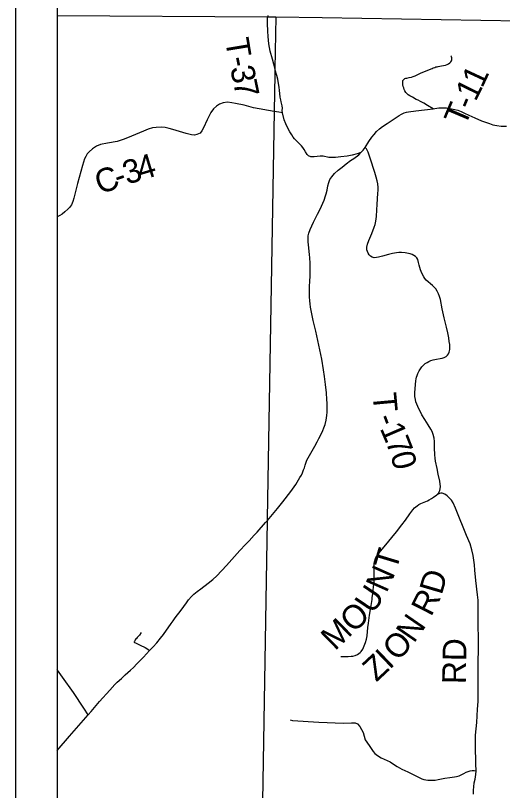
# Model space of a CAD drawing. Extents: x -10 to 158, y 8 to 33.
# Drawn here: x 148.504 to 149.672, y 28.282 to 30.14 of the extents above; entities that cross this region are included whole.
import ezdxf

# ---------------------------------------------------------------- set-up
doc = ezdxf.new("R2010")
doc.units = 0
for name, color, linetype in [('GM_X_County_Road', 7, 'Continuous'), ('GM_X_County_Road_Text', 7, 'Continuous'), ('GM_X_Township_Road', 7, 'Continuous'), ('GM_X_Township_Road_Text', 7, 'Continuous'), ('GM_X_Township_Text', 7, 'Continuous'), ('SH_Data', 7, 'Continuous')]:
    doc.layers.add(name, color=color, linetype=linetype)

msp = doc.modelspace()

# ---------------------------------------------------------------- linework, layer by layer
at = {"layer": 'GM_X_County_Road'}
for points in [[(149.1243, 29.9099), (149.0748, 29.9186), (149.0523, 29.9246), (149.032, 29.9293), (149.0225, 29.9306), (149.0121, 29.9318), (149.0023, 29.9303), (148.9936, 29.9271), (148.9857, 29.9228), (148.9789, 29.9163), (148.9726, 29.9075), (148.964, 29.8896), (148.955, 29.8705), (148.9505, 29.863), (148.9465, 29.858), (148.9392, 29.8543), (148.9331, 29.8531), (148.9263, 29.8535), (148.9135, 29.8566), (148.881, 29.8667), (148.8727, 29.8691), (148.8626, 29.8711), (148.8541, 29.8721), (148.8411, 29.8717), (148.8322, 29.8702), (148.8221, 29.8674), (148.8107, 29.8623), (148.8011, 29.8588), (148.7824, 29.8508), (148.7648, 29.8434), (148.7479, 29.8382), (148.7246, 29.834), (148.7076, 29.8304), (148.6984, 29.8265), (148.6884, 29.8199), (148.6804, 29.8131), (148.6758, 29.8079), (148.6722, 29.802), (148.6694, 29.7961), (148.6644, 29.7802), (148.6527, 29.7367), (148.6435, 29.7021), (148.6413, 29.6942), (148.6382, 29.6862), (148.6333, 29.6798), (148.6291, 29.6755), (148.6224, 29.6692), (148.6159, 29.6639), (148.6099, 29.66), (148.6038, 29.6571)], [(149.3325, 29.8115), (149.3234, 29.8082), (149.3113, 29.8049), (149.2997, 29.8028), (149.2842, 29.8012), (149.2716, 29.7998), (149.2636, 29.7994), (149.2558, 29.7996), (149.2421, 29.8025), (149.2347, 29.8026), (149.2203, 29.8009), (149.2121, 29.8014), (149.2066, 29.8036), (149.2037, 29.8067), (149.1996, 29.8129), (149.1963, 29.8188), (149.1934, 29.8234), (149.1901, 29.8275), (149.1828, 29.835), (149.1795, 29.8382), (149.1735, 29.8444), (149.1703, 29.8483), (149.1664, 29.8534), (149.1617, 29.8608), (149.1573, 29.8694), (149.1526, 29.8799), (149.1487, 29.8901), (149.144, 29.9067), (149.1353, 29.9083), (149.1243, 29.9099)], [(149.3427, 29.8238), (149.3513, 29.8378), (149.3586, 29.848), (149.3639, 29.8542), (149.3697, 29.8614), (149.3774, 29.8681), (149.3846, 29.8735), (149.3958, 29.8807), (149.4077, 29.889), (149.424, 29.9001), (149.4296, 29.9035), (149.4365, 29.9066), (149.4419, 29.908), (149.4464, 29.9086), (149.4642, 29.9111), (149.5055, 29.9164), (149.5099, 29.917), (149.5191, 29.9182), (149.5287, 29.9187), (149.5379, 29.9184), (149.5494, 29.9165), (149.5577, 29.9149), (149.5646, 29.9126), (149.5729, 29.9096), (149.5809, 29.9057), (149.591, 29.9011), (149.6056, 29.8946), (149.622, 29.8877), (149.6411, 29.8806), (149.6492, 29.8779), (149.6584, 29.8759), (149.6686, 29.8744), (149.682, 29.8743)], [(149.0833, 28.9014), (149.1037, 28.924), (149.108, 28.9288), (149.132, 28.9574), (149.1455, 28.9738), (149.1641, 28.9986), (149.1761, 29.015), (149.1863, 29.0321), (149.1896, 29.0374), (149.1922, 29.0434), (149.1951, 29.0502), (149.1969, 29.055), (149.1988, 29.0614), (149.2009, 29.069), (149.2029, 29.0736), (149.2056, 29.0791), (149.2216, 29.1076), (149.2275, 29.1179), (149.2315, 29.1253), (149.2369, 29.1357), (149.2412, 29.1447), (149.2438, 29.1514), (149.2464, 29.159), (149.2488, 29.1696), (149.2504, 29.1807), (149.2513, 29.1888), (149.2512, 29.1964), (149.2513, 29.2103), (149.251, 29.2191), (149.2496, 29.2353), (149.2475, 29.2548), (149.2453, 29.2742), (149.2429, 29.2901), (149.2387, 29.316), (149.2316, 29.3492), (149.2242, 29.3831), (149.2181, 29.4086), (149.2132, 29.4325), (149.2116, 29.4408), (149.2104, 29.4485), (149.2096, 29.456), (149.2088, 29.4653), (149.2091, 29.478), (149.2093, 29.4905), (149.2096, 29.5028), (149.2105, 29.5147), (149.2107, 29.5322), (149.2104, 29.5451), (149.2097, 29.56), (149.2091, 29.5657), (149.2067, 29.5909), (149.206, 29.5966), (149.2057, 29.6011), (149.2057, 29.6061), (149.2063, 29.6118), (149.2076, 29.6182), (149.2104, 29.6269), (149.2144, 29.6353), (149.2189, 29.6442), (149.2284, 29.6633), (149.2348, 29.6753), (149.238, 29.683), (149.244, 29.6975), (149.2475, 29.7073), (149.2492, 29.7121), (149.2512, 29.721), (149.2534, 29.7314), (149.2554, 29.7394), (149.2581, 29.7468), (149.2623, 29.7534), (149.2689, 29.7609), (149.2778, 29.7692), (149.2873, 29.7766), (149.2973, 29.7844), (149.3078, 29.7919), (149.3157, 29.7972), (149.3272, 29.8055), (149.3325, 29.8115), (149.3378, 29.8172), (149.3427, 29.8238)], [(148.6038, 28.3779), (148.6336, 28.4119), (148.6449, 28.4246), (148.6778, 28.4628), (148.6851, 28.4709), (148.7057, 28.4948), (148.7299, 28.5224), (148.7421, 28.5357), (148.7476, 28.5412), (148.7578, 28.5505), (148.7669, 28.5586), (148.7794, 28.5698), (148.787, 28.5769), (148.7953, 28.5851), (148.8028, 28.5931), (148.8106, 28.6015), (148.8253, 28.6171), (148.8266, 28.6187), (148.8338, 28.6264), (148.8425, 28.636), (148.8517, 28.6465), (148.8588, 28.6554), (148.8772, 28.6821), (148.8817, 28.6886), (148.8868, 28.6957), (148.9012, 28.7141), (148.9139, 28.7319), (148.9191, 28.7386), (148.9264, 28.7468), (148.9318, 28.7521), (148.94, 28.7587), (148.9486, 28.7655), (148.9657, 28.7787), (148.9773, 28.7876), (148.9868, 28.7963), (149.0101, 28.821), (149.0422, 28.8568), (149.0557, 28.8712), (149.064, 28.8805), (149.0762, 28.8936), (149.0785, 28.8962), (149.0833, 28.9014)]]:
    msp.add_lwpolyline(points, dxfattribs=at)
at = {"layer": 'GM_X_Township_Road'}
for points in [[(149.1329, 29.9869), (149.1305, 29.9959), (149.127, 30.0091), (149.1264, 30.0116), (149.1205, 30.0354), (149.1145, 30.0547), (149.1113, 30.072), (149.1104, 30.0804), (149.1096, 30.0898), (149.1089, 30.1026), (149.1082, 30.1208), (149.1085, 30.1359)], [(149.1095, 30.1402), (149.1085, 30.1359)], [(149.5055, 29.9164), (149.4922, 29.9242), (149.4833, 29.9295), (149.4752, 29.9338), (149.4697, 29.9367), (149.4653, 29.9389), (149.456, 29.9438), (149.4499, 29.9472), (149.446, 29.9498), (149.4425, 29.9528), (149.4401, 29.9554), (149.4376, 29.9592), (149.4363, 29.9622), (149.4351, 29.9662), (149.4342, 29.9695), (149.4333, 29.9735), (149.4329, 29.9765), (149.4327, 29.9798), (149.4328, 29.9818), (149.4332, 29.9838), (149.4343, 29.9855), (149.436, 29.9873), (149.438, 29.9886), (149.4405, 29.9897), (149.4424, 29.99), (149.448, 29.991), (149.4535, 29.9921), (149.4577, 29.9933), (149.4626, 29.9956), (149.4769, 30.0022), (149.5031, 30.0128), (149.506, 30.0142), (149.5095, 30.0155), (149.5124, 30.0165), (149.515, 30.0172), (149.5177, 30.0178), (149.5214, 30.0184), (149.5258, 30.0191), (149.5308, 30.0199), (149.535, 30.0209), (149.539, 30.0223), (149.5426, 30.0239), (149.5457, 30.0263), (149.5478, 30.0285), (149.5495, 30.0316), (149.5502, 30.0338), (149.5506, 30.0366), (149.5504, 30.0387), (149.5501, 30.0408), (149.5492, 30.0423), (149.548, 30.0436)], [(149.144, 29.9067), (149.1437, 29.9119), (149.144, 29.918), (149.1434, 29.9236), (149.1411, 29.9333), (149.14, 29.938), (149.139, 29.9441), (149.1381, 29.9532), (149.1373, 29.9603), (149.1364, 29.9678), (149.135, 29.9771), (149.1329, 29.9869)], [(149.2844, 28.603), (149.2882, 28.6027), (149.2954, 28.6028), (149.3018, 28.6029), (149.3088, 28.6034), (149.3131, 28.604), (149.3187, 28.6055), (149.324, 28.6079), (149.3278, 28.6104), (149.3303, 28.6124), (149.3327, 28.6152), (149.3368, 28.6208), (149.3389, 28.6245), (149.3405, 28.6286), (149.3432, 28.6365), (149.3456, 28.6447), (149.3471, 28.6527), (149.3491, 28.6726), (149.3504, 28.6829), (149.3534, 28.7021), (149.3574, 28.7255), (149.3592, 28.7393), (149.3596, 28.7433), (149.3608, 28.7542), (149.3626, 28.7697), (149.3639, 28.7819), (149.3644, 28.7915), (149.3644, 28.8074), (149.3641, 28.8154), (149.3643, 28.823), (149.3645, 28.8268), (149.3655, 28.832), (149.3667, 28.8359), (149.3685, 28.8402), (149.3706, 28.8435), (149.3732, 28.8474), (149.3796, 28.8553), (149.3925, 28.8708), (149.4065, 28.8883), (149.4175, 28.9021), (149.4306, 28.9188), (149.4392, 28.93), (149.4497, 28.9447), (149.4566, 28.9544), (149.4613, 28.9597), (149.467, 28.9645), (149.4713, 28.967), (149.4762, 28.9695), (149.488, 28.9747), (149.4921, 28.9765), (149.4965, 28.9787), (149.5014, 28.9814), (149.5067, 28.9849), (149.5145, 28.9905), (149.5184, 28.9948), (149.5204, 28.9977), (149.5218, 29.0006), (149.5227, 29.0051), (149.5233, 29.0103), (149.5229, 29.0165), (149.5218, 29.0235), (149.5177, 29.0403), (149.515, 29.0535), (149.5117, 29.0711), (149.5103, 29.0781), (149.5095, 29.0866), (149.5091, 29.1033), (149.5092, 29.1096), (149.5087, 29.1181), (149.5079, 29.1262), (149.5059, 29.1349), (149.5031, 29.1426), (149.5, 29.1483), (149.4936, 29.1582), (149.4855, 29.171), (149.4789, 29.1822), (149.475, 29.1893), (149.4713, 29.1968), (149.4664, 29.2077), (149.4644, 29.2139), (149.4632, 29.2188), (149.462, 29.2262), (149.4619, 29.2314), (149.4621, 29.236), (149.4642, 29.2636), (149.4648, 29.2685), (149.4659, 29.2729), (149.4672, 29.2768), (149.4688, 29.2817), (149.472, 29.2875), (149.475, 29.2924), (149.4789, 29.2972), (149.4823, 29.3013), (149.4867, 29.3052), (149.4911, 29.308), (149.4955, 29.3105), (149.5, 29.3123), (149.5054, 29.3139), (149.5135, 29.3157), (149.5222, 29.3171), (149.5274, 29.3183), (149.5324, 29.3198), (149.5366, 29.3221), (149.5401, 29.3253), (149.5424, 29.3285), (149.5445, 29.3329), (149.5457, 29.339), (149.5457, 29.3456), (149.5454, 29.3514), (149.5444, 29.3586), (149.5435, 29.3668), (149.5411, 29.379), (149.538, 29.3927), (149.5325, 29.4149), (149.5274, 29.4362), (149.523, 29.4588), (149.5212, 29.4664), (149.5189, 29.4728), (149.5157, 29.4789), (149.5123, 29.4843), (149.5089, 29.488), (149.5042, 29.4925), (149.4892, 29.5053), (149.4859, 29.5089), (149.483, 29.5136), (149.4787, 29.5223), (149.4754, 29.5301), (149.4736, 29.5356), (149.4724, 29.5416), (149.4708, 29.5476), (149.4688, 29.555), (149.4662, 29.5589), (149.463, 29.5621), (149.4594, 29.5646), (149.4555, 29.5666), (149.4503, 29.5684), (149.439, 29.5706), (149.43, 29.5714), (149.4237, 29.5713), (149.4181, 29.5712), (149.408, 29.5693), (149.3986, 29.5667), (149.3841, 29.5627), (149.3744, 29.5601), (149.3697, 29.5593), (149.3646, 29.5591), (149.3593, 29.5605), (149.3554, 29.5628), (149.352, 29.5661), (149.3495, 29.5699), (149.348, 29.5738), (149.347, 29.5783), (149.347, 29.5845), (149.3483, 29.5919), (149.3513, 29.6007), (149.3586, 29.6174), (149.3646, 29.6322), (149.3669, 29.639), (149.3676, 29.6425), (149.3683, 29.6468), (149.3696, 29.6583), (149.3705, 29.6743), (149.3714, 29.6867), (149.3731, 29.7141), (149.3735, 29.7202), (149.3737, 29.7274), (149.3728, 29.7361), (149.3713, 29.7434), (149.3691, 29.7522), (149.3659, 29.7638), (149.3545, 29.7979), (149.3495, 29.8126), (149.3477, 29.8167), (149.3457, 29.8202), (149.3427, 29.8238)], [(149.6022, 28.273), (149.6027, 28.2825), (149.6033, 28.2903), (149.6044, 28.3), (149.6065, 28.3091), (149.6082, 28.3198), (149.6091, 28.329), (149.6084, 28.3455), (149.6077, 28.3893), (149.6076, 28.4145), (149.6102, 28.4443), (149.6118, 28.4769), (149.6136, 28.4953), (149.6138, 28.5294), (149.6134, 28.5528), (149.6134, 28.5915), (149.6145, 28.6178), (149.6147, 28.6447), (149.6135, 28.6797), (149.6138, 28.7036), (149.614, 28.7133), (149.6139, 28.7228), (149.6134, 28.7379), (149.6122, 28.7505), (149.6083, 28.7849), (149.6059, 28.8096), (149.605, 28.8226), (149.6014, 28.8453), (149.5988, 28.8588), (149.5942, 28.8727), (149.586, 28.893), (149.5795, 28.9088), (149.5673, 28.9383), (149.5593, 28.9587), (149.5538, 28.9713), (149.5498, 28.9775), (149.5469, 28.981), (149.544, 28.9834), (149.5391, 28.9879), (149.5334, 28.9924), (149.5277, 28.9947), (149.524, 28.9948), (149.5206, 28.9941), (149.5145, 28.9905)], [(148.8054, 28.6603), (148.8013, 28.6541), (148.7984, 28.6508), (148.7961, 28.6485), (148.794, 28.6464), (148.7922, 28.6449), (148.7909, 28.6429), (148.7898, 28.6407), (148.789, 28.6391), (148.7888, 28.638), (148.7888, 28.6369), (148.7896, 28.6362), (148.7919, 28.6353), (148.8026, 28.6302), (148.8146, 28.6246), (148.8213, 28.6204), (148.8253, 28.6171)], [(148.6778, 28.4628), (148.6678, 28.4787), (148.6426, 28.5162), (148.6167, 28.5536), (148.6047, 28.5703), (148.6038, 28.5715)], [(149.1627, 28.4514), (149.168, 28.4498), (149.2312, 28.4451), (149.2908, 28.443), (149.3097, 28.444), (149.3185, 28.4439), (149.3245, 28.4416), (149.3301, 28.4347), (149.3376, 28.4206), (149.3427, 28.4031), (149.3526, 28.3892), (149.3587, 28.3797), (149.3619, 28.3748), (149.366, 28.3704), (149.3719, 28.3652), (149.3809, 28.3599), (149.3956, 28.3534), (149.4024, 28.3503), (149.4082, 28.3466), (149.4195, 28.339), (149.4308, 28.3324), (149.4451, 28.3261), (149.4606, 28.3186), (149.4785, 28.3098), (149.4832, 28.3077), (149.4929, 28.3065), (149.502, 28.3061), (149.5106, 28.3065), (149.5181, 28.3077), (149.5336, 28.3109), (149.5457, 28.3129), (149.5569, 28.3144), (149.562, 28.315), (149.5679, 28.3164), (149.5729, 28.3193), (149.579, 28.3223), (149.585, 28.3252), (149.5898, 28.3271), (149.5946, 28.3285), (149.5993, 28.3295), (149.604, 28.3295), (149.6091, 28.329)]]:
    msp.add_lwpolyline(points, dxfattribs=at)
at = {"layer": 'GM_X_Township_Text'}
msp.add_line((148.6038, 30.1399), (148.6038, 27.4428), dxfattribs=at)
for points in [[(148.6038, 30.1399), (149.1083, 30.1364), (149.1287, 30.1368), (149.2397, 30.1351), (150.0007, 30.1222), (150.0269, 30.1247), (150.6451, 30.1119), (150.6811, 30.1115), (151.1372, 30.1057), (152.063, 30.0899), (152.8656, 30.0723), (153.1825, 30.071), (153.2474, 30.0684), (153.3319, 30.0657), (153.3945, 30.0654), (153.6154, 30.0623), (153.6996, 30.0615), (153.7013, 30.1642), (153.702, 30.2085), (153.7021, 30.212), (153.7282, 31.2273), (153.7348, 31.8623)], [(153.7348, 31.8623), (148.6038, 31.8623), (148.6038, 30.1399)], [(149.1287, 30.1368), (149.1262, 30.0121), (149.1259, 29.9982), (149.1241, 29.9105), (149.1078, 28.9329), (149.1078, 28.9293), (149.083, 27.4378), (148.9976, 27.4386), (148.6038, 27.4428), (148.6038, 25.0623), (153.6265, 25.0623)]]:
    msp.add_lwpolyline(points, dxfattribs=at)
at = {"layer": 'SH_Data'}
for p, q in [((148.5038, 31.9623), (148.5038, 24.9623)), ((148.6038, 31.8623), (148.6038, 25.0623))]:
    msp.add_line(p, q, dxfattribs=at)

# ---------------------------------------------------------------- texts
at = {"layer": 'GM_X_County_Road_Text'}
for s, rotation, p in [('4', 16.7167, (148.8049, 29.7443)), ('3', 17.8458, (148.7718, 29.7337)), ('C', 20.2038, (148.7066, 29.7102)), ('-', 19.02, (148.7501, 29.7262))]:
    msp.add_text(s, height=0.0568, rotation=rotation, dxfattribs=at).set_placement(p)
at = {"layer": 'GM_X_Township_Road_Text'}
for s, height, rotation, p in [('T', 0.0568, 279.3424, (149.0066, 30.0815)), ('-', 0.0568, 281.3915, (149.0139, 30.0374)), ('3', 0.0568, 281.6535, (149.0185, 30.0145)), ('1', 0.0568, 65.0078, (149.6235, 29.9642)), ('7', 0.0568, 281.757, (149.0256, 29.9804)), ('1', 0.0568, 63.7584, (149.6075, 29.9316)), ('-', 0.0568, 67.0433, (149.5987, 29.9109)), ('T', 0.0568, 67.0788, (149.5822, 29.8718)), ('T', 0.0568, 275.2573, (149.3603, 29.2331)), ('-', 0.0568, 290.4386, (149.3678, 29.1748)), ('1', 0.0568, 293.2345, (149.3771, 29.1502)), ('7', 0.0568, 291.4149, (149.3907, 29.1184)), ('0', 0.0568, 283.9706, (149.4029, 29.0877)), ('T', 0.0568, 73.2772, (149.4169, 28.8066)), ('N', 0.0568, 66.0455, (149.3939, 28.7536)), ('D', 0.0568, 73.6408, (149.5261, 28.7487)), ('U', 0.0568, 56.1315, (149.3609, 28.7027)), ('R', 0.0568, 63.2907, (149.501, 28.6966)), ('O', 0.0568, 42.3278, (149.3142, 28.6577)), ('M', 0.0568, 44.2585, (149.2704, 28.615)), ('N', 0.0568, 55.4169, (149.4596, 28.6329)), ('O', 0.0568, 48.0129, (149.4212, 28.5895)), ('RD', 0.05682, 89.0127, (149.584, 28.5364)), ('I', 0.0568, 43.7437, (149.4011, 28.57)), ('Z', 0.0568, 43.0359, (149.3695, 28.5405))]:
    msp.add_text(s, height=height, rotation=rotation, dxfattribs=at).set_placement(p)

doc.saveas('drawing.dxf')
